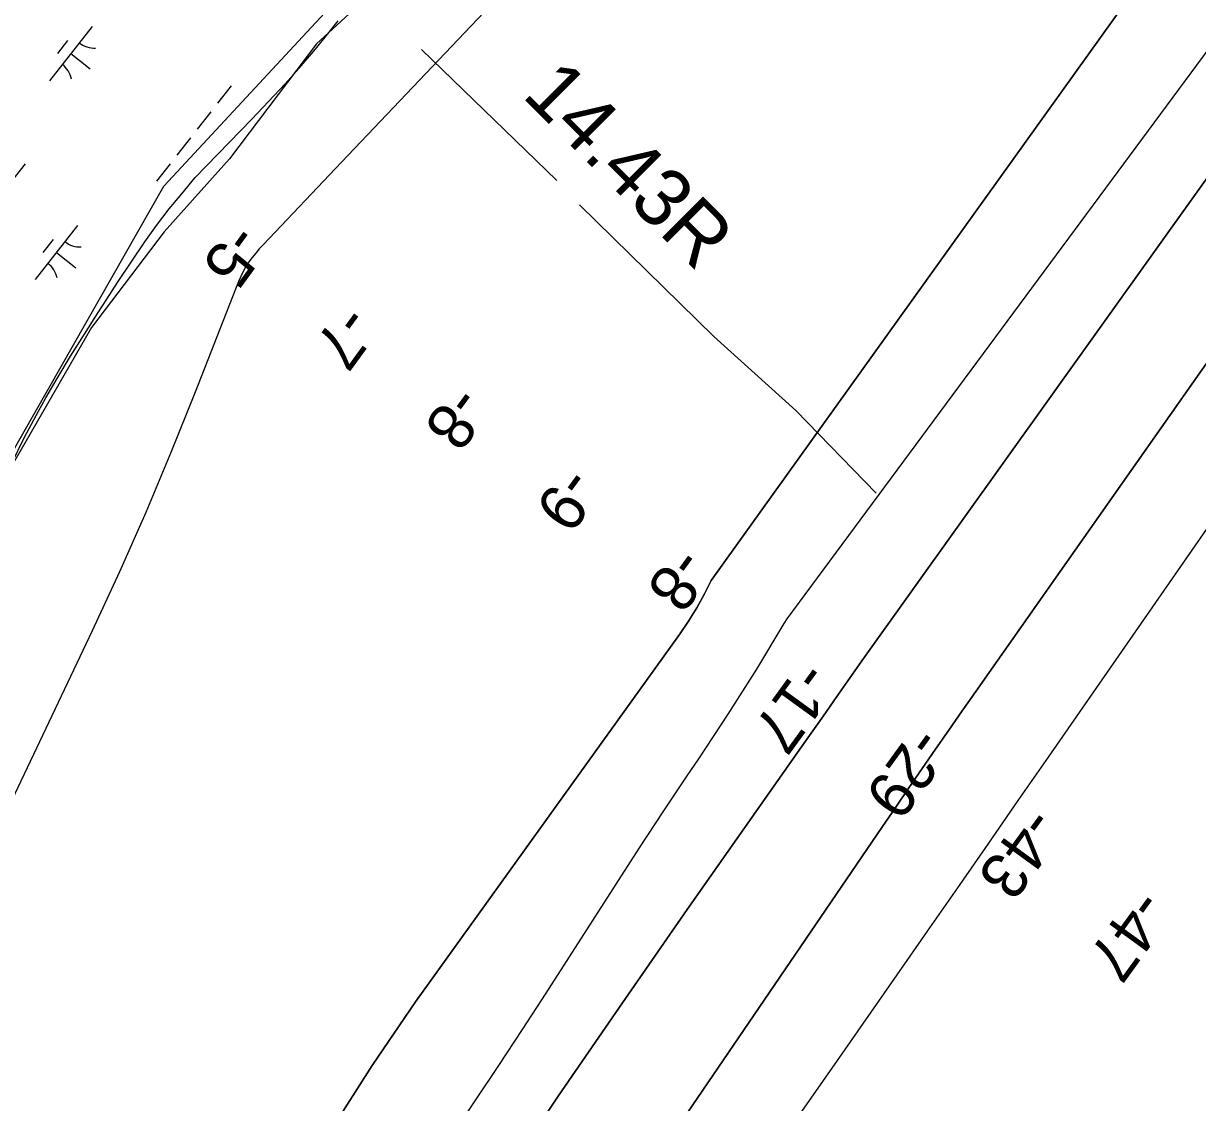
# Model space of a CAD drawing. Extents: x 3896831 to 3918110, y 171006 to 193349.
# Drawn here: x 3905096 to 3905950, y 177993 to 178777 of the extents above; entities that cross this region are included whole.
import ezdxf

# ---------------------------------------------------------------- set-up
doc = ezdxf.new("R2010")
doc.units = 0
for name, color, linetype in [('V-LEVE-TOET', 7, 'Continuous'), ('V-RIVR-EDGE', 7, 'Continuous'), ('V-RIVR-RANG', 7, 'Continuous'), ('V-RRAP-FSHR', 7, 'Continuous'), ('V-STRM-FMON', 7, 'Continuous'), ('V-TOPO-DPTH', 7, 'Continuous'), ('V-TOPO-MINR', 7, 'Continuous'), ('V-WETL-SWMP', 7, 'Continuous')]:
    doc.layers.add(name, color=color, linetype=linetype)

msp = doc.modelspace()

# ---------------------------------------------------------------- linework, layer by layer
at = {"layer": 'V-LEVE-TOET'}
msp.add_line((3905385.31, 178757.92), (3905483.56, 178662.57), dxfattribs=at)
msp.add_lwpolyline([(3905500.26, 178644.94), (3905597.75, 178549.19), (3905657.52, 178495.61), (3905715.79, 178435.46)], dxfattribs=at)
at = {"layer": 'V-RIVR-EDGE'}
msp.add_lwpolyline([(3905758.5, 179231.3), (3905700.89, 179183.91), (3905629.34, 179122.59), (3905601.46, 179105.86), (3905585.66, 179080.77), (3905565.22, 179066.83), (3905542.92, 179038.03), (3905505.75, 178985.99), (3905489.03, 178959.97), (3905365.44, 178814.09), (3905308.76, 178762.05), (3905245.57, 178678.42), (3905198.18, 178625.46), (3905145.22, 178555.77), (3905077.39, 178438.69), (3905057.87, 178407.1), (3905028.14, 178332.76), (3905014.2, 178297.45), (3904987.25, 178241.7), (3904936.15, 178133.91), (3904919.42, 178106.03), (3904912.92, 178070.72), (3904845.08, 177972.22)], dxfattribs=at)
at = {"layer": 'V-RRAP-FSHR'}
msp.add_lwpolyline([(3903099.01, 175512.15), (3904431.09, 177312.94), (3905197.83, 178658.46), (3906088.44, 179617.35), (3906806.67, 180565.1), (3907065.24, 181038.97), (3907795.13, 181990.69)], dxfattribs=at)
at = {"layer": 'V-TOPO-DPTH'}
for points in [[(3906816.56, 179906.15), (3906799.1, 179875.59), (3906781.64, 179845.02), (3906764.17, 179814.47), (3906746.35, 179784.12), (3906728.08, 179754.07), (3906709.11, 179724.44), (3906689.69, 179695.1), (3906629.5, 179606.46), (3906616.93, 179588.11), (3906604.24, 179569.85), (3906591.4, 179551.7), (3906578.44, 179533.63), (3906549.52, 179493.69), (3905705.47, 178313.64)], [(3905705.47, 178313.64), (3906549.52, 179493.69), (3906578.44, 179533.63), (3906591.4, 179551.7), (3906604.24, 179569.85), (3906616.93, 179588.11), (3906629.5, 179606.46), (3906689.69, 179695.1), (3906709.11, 179724.44), (3906728.08, 179754.07), (3906746.35, 179784.12), (3906764.17, 179814.47), (3906781.64, 179845.02), (3906799.1, 179875.59), (3906816.56, 179906.15)], [(3905319.17, 177971.87), (3905349.27, 178019.32), (3905380.97, 178065.8), (3905572.88, 178332.71), (3905579.35, 178342.28), (3905585.44, 178352.07), (3905590.96, 178362.2), (3905595.84, 178372.04), (3906471.64, 179592.95)], [(3906272.08, 178979.19), (3905798.06, 178305.1), (3905788.28, 178291.17), (3905778.52, 178277.22), (3905768.79, 178263.26), (3905759.07, 178249.29), (3905749.38, 178235.29), (3905739.72, 178221.28), (3905730.09, 178207.25), (3905720.49, 178193.2), (3905350.87, 177651.04)], [(3905350.87, 177651.04), (3905720.49, 178193.2), (3905730.09, 178207.25), (3905739.72, 178221.28), (3905749.38, 178235.29), (3905759.07, 178249.29), (3905768.79, 178263.26), (3905778.52, 178277.22), (3905788.28, 178291.17), (3905798.06, 178305.1), (3906272.08, 178979.19)], [(3906209.97, 178774.76), (3905840.99, 178243.64), (3905818.99, 178211.98), (3905796.99, 178180.33), (3905774.98, 178148.67), (3905752.97, 178117.02), (3905740.39, 178098.93), (3905712.07, 178058.25), (3905683.73, 178017.58), (3905655.36, 177976.93)], [(3906209.97, 178774.76), (3905840.99, 178243.64), (3905818.99, 178211.98), (3905796.99, 178180.33), (3905774.98, 178148.67), (3905752.97, 178117.02), (3905740.39, 178098.93), (3905712.07, 178058.25), (3905683.73, 178017.58), (3905655.36, 177976.93)], [(3905705.47, 178313.64), (3905685.1, 178284.47), (3905679.25, 178276.09), (3905673.38, 178267.71), (3905667.51, 178259.35), (3905661.63, 178250.98), (3905578.46, 178132.79), (3905531.34, 178065.09), (3905484.69, 177997.07), (3905438.75, 177928.57)], [(3905438.75, 177928.57), (3905484.69, 177997.07), (3905531.34, 178065.09), (3905578.46, 178132.79), (3905661.63, 178250.98), (3905667.51, 178259.35), (3905673.38, 178267.71), (3905679.25, 178276.09), (3905685.1, 178284.47), (3905705.47, 178313.64)]]:
    msp.add_lwpolyline(points, dxfattribs=at)
at = {"layer": 'V-TOPO-MINR'}
for points in [[(3906777.53, 179925.03), (3906738.99, 179861.58), (3906701.53, 179797.46), (3906636.7, 179683.13), (3906632.47, 179675.66), (3906628.23, 179668.19), (3906623.99, 179660.73), (3906619.75, 179653.26), (3906615.42, 179645.84), (3906610.98, 179638.5), (3906606.36, 179631.27), (3906601.62, 179624.11), (3906586.52, 179601.87), (3906583.39, 179597.33), (3906580.2, 179592.83), (3906576.95, 179588.38), (3906573.64, 179583.96), (3906562, 179568.68), (3906552.55, 179556.92), (3906542.7, 179545.51), (3906532.43, 179534.8), (3905650.82, 178344.2)], [(3906816.56, 179906.15), (3906799.1, 179875.59), (3906781.64, 179845.02), (3906764.17, 179814.47), (3906746.35, 179784.12), (3906728.08, 179754.07), (3906709.11, 179724.44), (3906689.69, 179695.1), (3906629.5, 179606.46), (3906616.93, 179588.11), (3906604.24, 179569.85), (3906591.4, 179551.7), (3906578.44, 179533.63), (3906549.52, 179493.69), (3905705.47, 178313.64)], [(3906393.42, 179815.82), (3906366.64, 179775.28), (3906360.37, 179766.27), (3906353.82, 179757.48), (3906346.85, 179749.02), (3906339.61, 179740.78), (3906332.13, 179732.71), (3906324.63, 179724.67), (3906317.13, 179716.71), (3905327.15, 178676.1)], [(3906471.64, 179592.95), (3905595.84, 178372.04), (3905590.96, 178362.2), (3905585.44, 178352.07), (3905579.35, 178342.28), (3905572.88, 178332.71), (3905380.97, 178065.8), (3905349.27, 178019.32), (3905319.17, 177971.87)], [(3906272.08, 178979.19), (3905798.06, 178305.1), (3905788.28, 178291.17), (3905778.52, 178277.22), (3905768.79, 178263.26), (3905759.07, 178249.29), (3905749.38, 178235.29), (3905739.72, 178221.28), (3905730.09, 178207.25), (3905720.49, 178193.2), (3905350.87, 177651.04)], [(3906209.97, 178774.76), (3905840.99, 178243.64), (3905818.99, 178211.98), (3905796.99, 178180.33), (3905774.98, 178148.67), (3905752.97, 178117.02), (3905740.39, 178098.93), (3905712.07, 178058.25), (3905683.73, 178017.58), (3905655.36, 177976.93)], [(3905327.15, 178676.1), (3905269.99, 178616.02), (3905267.26, 178613.03), (3905264.63, 178609.95), (3905262.15, 178606.76), (3905259.76, 178603.49), (3905257.56, 178600.1), (3905255.54, 178596.61), (3905253.76, 178592.99), (3905252.16, 178589.28), (3905220.68, 178508.81), (3905203, 178464.99), (3905184.71, 178421.44), (3905165.51, 178378.28), (3905145.69, 178335.39), (3904814.59, 177638.25)], [(3905650.82, 178344.2), (3905648.79, 178340.72), (3905628.77, 178307.48), (3905607.95, 178274.74), (3905586.6, 178242.31), (3905578.27, 178230), (3905560.82, 178203.9), (3905543.53, 178177.69), (3905526.48, 178151.33), (3905509.6, 178124.85), (3905492.74, 178098.37), (3905475.74, 178071.97), (3905458.53, 178045.71), (3905441.19, 178019.54), (3905407.68, 177969.44)], [(3905705.47, 178313.64), (3905685.1, 178284.47), (3905679.25, 178276.09), (3905673.38, 178267.71), (3905667.51, 178259.35), (3905661.63, 178250.98), (3905578.46, 178132.79), (3905531.34, 178065.09), (3905484.69, 177997.07), (3905438.75, 177928.57)]]:
    msp.add_lwpolyline(points, dxfattribs=at)
at = {"layer": 'V-WETL-SWMP'}
for p, q in [((3905317.15, 178769.31), (3905324.53, 178778.86)), ((3905145.63, 178774.6), (3905114.78, 178735.25)), ((3905308.25, 178758.22), (3905317.15, 178769.31)), ((3905127.83, 178764.41), (3905120.43, 178754.97)), ((3905296.29, 178744.28), (3905308.25, 178758.22)), ((3905130.2, 178754.93), (3905144.37, 178743.82)), ((3905286.1, 178732.92), (3905296.29, 178744.28)), ((3905261.9, 178707.35), (3905286.1, 178732.92)), ((3905246.82, 178731.4), (3905236.95, 178718.81)), ((3905220.63, 178664.98), (3905261.9, 178707.35)), ((3905232.02, 178712.51), (3905222.15, 178699.92)), ((3905217.21, 178693.62), (3905207.34, 178681.03)), ((3905096.95, 178674.86), (3905087.08, 178662.27)), ((3905202.41, 178674.73), (3905192.54, 178662.14)), ((3905210.96, 178653.11), (3905220.63, 178664.98)), ((3905201.8, 178642.01), (3905210.96, 178653.11)), ((3905192.39, 178629.89), (3905201.8, 178642.01)), ((3905135.15, 178630.05), (3905104.31, 178590.69)), ((3905184.01, 178618.02), (3905192.39, 178629.89)), ((3905117.36, 178619.85), (3905109.96, 178610.41)), ((3905164.2, 178588.63), (3905184.01, 178618.02)), ((3905119.73, 178610.37), (3905133.9, 178599.27)), ((3905156.33, 178576.52), (3905164.2, 178588.63)), ((3905149.98, 178566.73), (3905156.33, 178576.52)), ((3905140.08, 178551), (3905149.98, 178566.73)), ((3905129.93, 178535.03), (3905140.08, 178551)), ((3905120.29, 178518.79), (3905129.93, 178535.03)), ((3905111.93, 178504.62), (3905120.29, 178518.79)), ((3905106.6, 178495.09), (3905111.93, 178504.62)), ((3905096.47, 178476.03), (3905106.6, 178495.09)), ((3905087.11, 178456.72), (3905096.47, 178476.03))]:
    msp.add_line(p, q, dxfattribs=at)
for centre, start, end in [((3905147.43, 178776.52), 231.14028, 272.68394), ((3905113.35, 178733.04), 11.14028, 52.68394), ((3905136.96, 178631.96), 231.14028, 272.68394), ((3905102.88, 178588.48), 11.14028, 52.68394)]:
    msp.add_arc(centre, 17.62, start, end, dxfattribs=at)

# ---------------------------------------------------------------- texts
at = {"layer": 'V-RIVR-RANG'}
for s, rotation, p in [('-5', 233.88833, (3905248, 178633.5)), ('-7', 233.88833, (3905328.46, 178574.12)), ('-8', 233.88833, (3905409.54, 178515.59)), ('-9', 233.88833, (3905490.24, 178456.53)), ('-8', 233.88833, (3905571.4, 178398.1)), ('-17', 234.04178, (3905662.06, 178315.4)), ('-29', 234.04178, (3905744.58, 178267.88)), ('-43', 234.04178, (3905826.65, 178209.35)), ('-47', 234.04178, (3905905.63, 178149.64))]:
    msp.add_text(s, height=33.5, rotation=rotation, dxfattribs=at).set_placement(p)
at = {"layer": 'V-STRM-FMON'}
msp.add_text('14.43R', height=42, rotation=315.01987, dxfattribs=at).set_placement((3905457.67, 178723.95))

doc.saveas('drawing.dxf')
